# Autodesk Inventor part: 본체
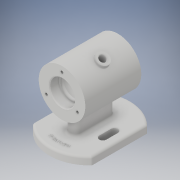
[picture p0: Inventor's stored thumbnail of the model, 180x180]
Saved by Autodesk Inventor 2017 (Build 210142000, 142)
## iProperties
Part Number: 본체
Material: 일반
Document SubType Name: Modeling
Designer: 601-13
Density: 1 g/cm^3
Appearance: 기본값
Author: 601-13
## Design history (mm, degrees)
sketch "스케치1"
  geometry: L1 (35.496, -38)-(-35.496, -38); L2 (35.496, 38)-(-35.496, 38); A1 r 52 centre (0, 0) between (-35.496, 38) and (-35.496, -38); A2 r 52 centre (0, 0) between (35.496, -38) and (35.496, 38); 3 further points
  constraints: 4 end point, 4 point on circle, 2 centre point, 2 horizontal, 2 midpoint, 2 vertical alignment, 1 coincident
  dimensions: "d2" = 76 distance between parallel lines of L2 L1; "d3" = 38 distance from line of L2 point (0, 0)
extrude "돌출1" new body sketch "스케치1" stored distance "d4" = 10; taper "d5" = 0 deg
sketch "스케치2"
  geometry: L1 (-19, 0)-(19, 0); L2 (-19, -7)-(19, -7); L3 (19, 7)-(-19, 7); L4 (-7.5, 24)-(7.5, 24); L5 (-7.5, 19.5)-(7.5, 19.5); L6 (7.5, 28.5)-(-7.5, 28.5); L7 (7.5, -28.5)-(-7.5, -28.5); L8 (-7.5, -19.5)-(7.5, -19.5); A1 r 7 centre (-19, 0) between (-19, 7) and (-19, -7); A2 r 7 centre (19, 0) between (19, -7) and (19, 7); A3 r 4.5 centre (-7.5, 24) between (-7.5, 28.5) and (-7.5, 19.5); A4 r 4.5 centre (7.5, 24) between (7.5, 19.5) and (7.5, 28.5); A5 r 4.5 centre (-7.5, -24) between (-7.5, -19.5) and (-7.5, -28.5); A6 r 4.5 centre (7.5, -24) between (7.5, -28.5) and (7.5, -19.5); 3 further points
  constraints: 20 end point, 12 point on circle, 8 tangent, 6 centre point, 6 symmetric about line, 2 horizontal, 2 midpoint, 2 parallel, 1 coincident, 1 vertical alignment, 2 other
  dimensions: "d6" = 14 diameter of A2; "d7" = 38 distance of L1.end L1.start; "d8" = 14 distance between parallel lines of L2 L3 (derived); "d9" = 9 diameter of A4; "d10" = 24 distance of point (0, 0) point (0, 24); "d11" = 15 distance of L4.end L4.start
node "작업 평면3"
sketch "스케치8"
  geometry: C1 r 42.5 at (0, 0); 1 further point
  constraints: 1 centre point, 1 coincident, 1 other
  dimensions: "d67" = 85 diameter of C1
feature "엠보싱2" sketch "스케치8" dims "d2" = 76, "d3" = 38, "d68" = 0.5, "d69" = 0
extrude "돌출2" cut sketch "스케치2" stored distance "d12" = 10; taper "d13" = 0 deg
sketch "스케치3"
  geometry: L1 (-36, 57)-(-36, 73); L2 (-36, 73)-(-24, 73); L3 (-24, 73)-(-24, 71); L4 (-24, 71)-(-20, 71); L5 (-20, 71)-(-20, 74.4); L6 (-20, 74.4)-(20, 74.4); L7 (20, 74.4)-(20, 71); L8 (20, 71)-(24, 71); L9 (24, 71)-(24, 73); L10 (24, 73)-(36, 73); L11 (36, 73)-(36, 57); L12 (36, 57)-(-36, 57); L13 (-36, 57)-(-36, 87); L14 (-36, 87)-(36, 87); L15 (36, 87)-(36, 57); L16 (35.496, -5)-(-35.496, -5) reference; 3 further points
  constraints: 30 end point, 11 perpendicular, 4 point on line, 2 midpoint, 2 vertical, 2 vertical alignment
  dimensions: "d14" = 16 distance of L1.start L1.end; "d15" = 14 distance between parallel lines of L12 L4; "d16" = 12 distance of L1.end L2.end; "d17" = 48 distance between parallel lines of L9 L3; "d18" = 40 distance between parallel lines of L7 L5; "d19" = 4 distance of L3.end L4.end; "d20" = 4 distance of L7.end L8.end (derived); "d21" = 12 distance of L9.end L10.end (derived); "d22" = 72 distance of L13.end L14.end (derived); "d23" = 30 distance of L1.start L13.end; "d31" = 62 distance from line of L16 point (0, 57)
revolve "회전1" stored, may be unused: angle "d25" = 90 deg
revolve "회전2" stored, may be unused: angle "d26" = 90 deg
extrude "돌출3" join sketch "스케치2" stored distance "d27" = 29; taper "d28" = 0 deg
sketch "스케치4" dims "d33" = 46
  geometry: L1 (-38, -62)-(38, -62) reference; 3 further points
  constraints: 2 vertical alignment, 2 other
  dimensions: "d32" = 62 distance from line of L1 point (0, 0)
hole "구멍1" sketch "스케치4" at (0, 23) diameter "d34" = 3.242; stored, may be unused: countersink angle "d38" = 90 deg, drill point angle "d40" = 118 deg; dims "d35" = 8, "d36" = 4, "d37" = 2, "d39" = 10
sketch "스케치5"
  geometry: L1 (57, 0)-(102.762, 0); L2 (57, 0)-(85.579, -16.5); C1 r 14 at (57, 0) reference; 1 further point
  constraints: 4 end point, 1 horizontal
  dimensions: "d44" = 30 deg angle of L1 L2; "d45" = 33 distance of L1.start L2.end
node "작업 평면1"
sketch "스케치6"
  geometry: C1 r 8 at (0, 0); C2 r 4 at (0, 0); 1 further point
  constraints: 2 centre point, 1 coincident
  dimensions: "d46" = 16 diameter of C1; "d47" = 8 diameter of C2
extrude "돌출4" join sketch "스케치6" stored distance "d48" = 29; taper "d49" = 0 deg
extrude "돌출5" cut sketch "스케치6" stored distance "d50" = 29; taper "d51" = 0 deg
fillet "모깎기1" dims "d52" = 1
fillet "모깎기2" dims "d53" = 1
fillet "모깎기3" dims "d57" = 0.3
fillet "모깎기4" dims "d58" = 0.3
fillet "모깎기5" dims "d59" = 3
fillet "모깎기6" dims "d60" = 3
chamfer "모따기1" distance "d61" = 1; stored, may be unused: second distance "d62" = 2, angle "d63" = 45 deg
fillet "모깎기7" dims "d64" = 3
node "솔리드1"
pattern_circular "원형 패턴1" dims angle "d42" = 360 deg
mirror "미러1"
other parameters: "d0" = 104, "d66" = 36
